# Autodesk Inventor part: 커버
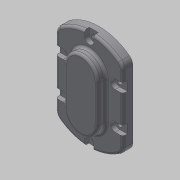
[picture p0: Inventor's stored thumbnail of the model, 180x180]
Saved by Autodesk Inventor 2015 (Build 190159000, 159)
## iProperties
Created: 2019-03
Part Number: 커버
Material: 알루미늄 6061
Document SubType Name: Modeling
Designer: mduedu
Density: 1 g/cm^3
Appearance: 기본값
Author: mduedu
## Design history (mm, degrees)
sketch "스케치1"
  geometry: L1 (44.721, -40)-(-44.721, -40); L2 (44.721, 40)-(-44.721, 40); A1 r 60 centre (0, 0) between (44.721, -40) and (44.721, 40); A2 r 60 centre (0, 0) between (-44.721, 40) and (-44.721, -40); 5 further points
  constraints: 6 point on circle, 4 end point, 2 centre point, 2 coincident, 2 horizontal alignment, 2 midpoint, 2 vertical alignment, 1 horizontal, 1 parallel
  dimensions: "d0" = 60 radius of A1; "d2" = 80 distance between parallel lines of L2 L1; "d3" = 120 distance of point (-60, 0) point (60, 0) (derived)
extrude "돌출1" new body sketch "스케치1" distance "d4" = 12; taper "d5" = 0 deg
sketch "스케치2"
  geometry: L1 (-20, -22)-(20, -22); L2 (20, -22)-(20, 22); L3 (20, 22)-(-20, 22); L4 (-20, 22)-(-20, -22); L5 (-20, -22)-(20, 22); L6 (20, -22)-(-20, 22); 3 further points
  constraints: 12 end point, 4 midpoint, 2 horizontal alignment, 2 parallel, 1 horizontal, 1 perpendicular, 4 other
  dimensions: "d6" = 40 distance between parallel lines of L2 L4; "d8" = 44 distance between parallel lines of L1 L3
extrude "돌출2" join sketch "스케치2" distance "d9" = 10; taper "d10" = 0 deg
fillet "모깎기1" dims "d11" = 10
fillet "모깎기2" dims "d12" = 3
sketch "스케치3"
  geometry: L1 (31, -22)-(31, 22); L2 (-31, 22)-(-31, -22); L3 (-31, -22)-(31, 22); L4 (31, -22)-(-31, 22); A1 r 31 centre (0, 22) between (31, 22) and (-31, 22); A2 r 31 centre (0, -22) between (-31, -22) and (31, -22); 7 further points
  constraints: 8 end point, 6 point on circle, 4 coincident, 3 tangent, 2 centre point, 2 midpoint, 1 parallel, 1 vertical, 1 vertical alignment
  dimensions: "d13" = 31 radius of A1; "d15" = 44 distance of A2.centre A1.centre
hole "구멍2" sketch "스케치3" at (-31, 22), (-31, -22), (31, -22), (31, 22), (0, 53), (0, -53) diameter "d28" = 5.5; stored, may be unused: countersink angle "d32" = 90 deg, drill point angle "d34" = 118 deg; dims "d29" = 6, "d30" = 4, "d31" = 2, "d33" = 8
sketch "스케치5"
  geometry: L1 (-40, 40)-(-40, -40) reference; L2 (40, -40)-(40, 40) reference; L3 (-5.5, 53)-(-5.5, 59.747); L4 (5.5, 53)-(5.5, 59.747); L5 (-31, 27.5)-(-40, 27.5); L6 (-31, 16.5)-(-40, 16.5); L7 (-31, -16.5)-(-40, -16.5); L8 (-31, -27.5)-(-40, -27.5); L9 (-5.5, -53)-(-5.5, -59.747); L10 (5.5, -53)-(5.5, -59.747); L11 (31, -27.5)-(40, -27.5); L12 (31, -16.5)-(40, -16.5); L13 (31, 16.5)-(40, 16.5); L14 (31, 27.5)-(40, 27.5); C1 r 2.75 at (0, 53) reference; C2 r 2.75 at (-31, 22) reference; C3 r 2.75 at (-31, -22) reference; C4 r 2.75 at (0, -53) reference; C5 r 2.75 at (31, -22) reference; C6 r 2.75 at (31, 22) reference; A1 r 60 centre (0, 0) between (36, 48) and (-36, 48) reference; A2 r 10 centre (-30, 40) between (-36, 48) and (-40, 40) reference; A3 r 10 centre (-30, -40) between (-40, -40) and (-36, -48) reference; A4 r 60 centre (0, 0) between (-36, -48) and (36, -48) reference; A5 r 10 centre (30, -40) between (36, -48) and (40, -40) reference; A6 r 10 centre (30, 40) between (40, 40) and (36, 48) reference; A7 r 5.5 centre (0, 53) between (-5.5, 53) and (5.5, 53); A8 r 5.5 centre (-31, 22) between (-31, 16.5) and (-31, 27.5); A9 r 5.5 centre (-31, -22) between (-31, -27.5) and (-31, -16.5); A10 r 5.5 centre (0, -53) between (5.5, -53) and (-5.5, -53); A11 r 5.5 centre (31, -22) between (31, -16.5) and (31, -27.5); A12 r 5.5 centre (31, 22) between (31, 27.5) and (31, 16.5); 1 further point
  constraints: 24 end point, 16 point on circle, 12 tangent, 8 parallel, 8 point on line, 6 centre point, 5 concentric, 4 horizontal, 1 coincident, 1 vertical
  dimensions: "d35" = 11 diameter of A7; "d36" = 11 diameter of A8; "d37" = 11 diameter of A9; "d38" = 11 diameter of A10; "d39" = 11 diameter of A11; "d40" = 11 diameter of A12
extrude "돌출4" cut sketch "스케치5" distance "d41" = 5.4; taper "d42" = 0 deg
sketch "스케치6"
  geometry: C1 r 12.5 at (0, 22); 1 further point
  constraints: 1 centre point, 1 vertical alignment
  dimensions: "d43" = 25 diameter of C1; "d45" = 22 distance of C1.centre point (0, 0)
extrude "돌출5" cut sketch "스케치6" distance "d47" = 15; taper "d48" = 0 deg
node "솔리드1"
mirror "대칭1"
